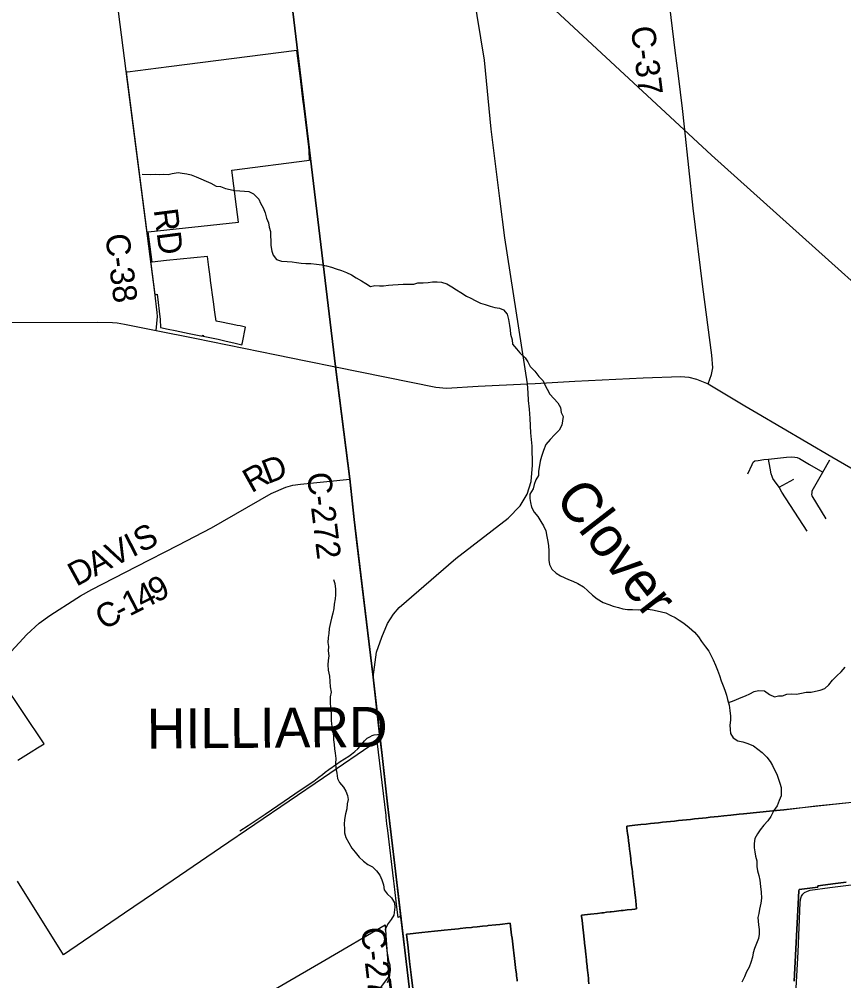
# Model space of a CAD drawing. Extents: x 114604 to 551442, y 316898 to 567001.
# Drawn here: x 149788 to 160095, y 405241 to 417252 of the extents above; entities that cross this region are included whole.
import ezdxf

# ---------------------------------------------------------------- set-up
doc = ezdxf.new("R2010")
doc.units = 0
for name, color, linetype in [('GE_P_Alignment_1000_Bearings', 7, 'Continuous'), ('GE_P_Alignment_100_Cardinal_Points', 7, 'Continuous'), ('GE_P_Alignment_100_Stations', 7, 'Continuous'), ('GE_P_Alignment_500_Bearings', 7, 'Continuous'), ('GE_P_Alignment_500_Distances', 7, 'Continuous'), ('PM_P_Cells', 7, 'Continuous'), ('PM_P_CL_Double_Solid', 7, 'Continuous'), ('PM_P_Stop_Line', 7, 'Continuous'), ('SH_Named_Boundary', 7, 'Continuous')]:
    doc.layers.add(name, color=color, linetype=linetype)

msp = doc.modelspace()

# ---------------------------------------------------------------- linework, layer by layer
at = {"layer": 'GE_P_Alignment_1000_Bearings'}
msp.add_lwpolyline([(147203, 425812), (147532, 425512), (151087, 422349), (154540, 419172), (158440, 415556), (161813, 412533), (168064, 407288)], dxfattribs=at)
at = {"layer": 'GE_P_Alignment_100_Cardinal_Points'}
msp.add_line((159289, 411408), (159471, 411506), dxfattribs=at)
for points in [[(158897, 411574), (158948, 411691), (158961, 411721), (158983, 411734), (159023, 411742), (159095, 411751), (159155, 411757), (159378, 411782), (159444, 411784), (159482, 411783), (159512, 411777), (159542, 411763), (159665, 411692), (159832, 411596)], [(159637, 410856), (159322, 411344), (159289, 411408), (159227, 411488), (159207, 411515), (159201, 411539), (159188, 411573), (159176, 411645), (159155, 411757)], [(159875, 411011), (159700, 411298), (159694, 411316), (159698, 411336), (159698, 411360), (159716, 411392), (159832, 411596), (159919, 411748)], [(152546, 407112), (152650, 407179), (152863, 407323), (153098, 407483), (153301, 407621), (153469, 407735), (153534, 407783), (153578, 407819), (153612, 407845), (153658, 407881), (153754, 407947), (153802, 407979), (153908, 408048), (153942, 408073), (153985, 408105), (154020, 408139), (154051, 408173), (154074, 408202), (154104, 408238), (154139, 408271), (154171, 408290), (154201, 408304), (154227, 408311), (154267, 408319), (154293, 408321)], [(159397, 402966), (159416, 403344), (159434, 403792), (159476, 404743), (159491, 405001), (159524, 405599), (159550, 406219), (159557, 406272), (159567, 406297), (159582, 406321), (159606, 406345), (159640, 406362), (159673, 406372), (159920, 406405), (160715, 406504), (161064, 406553), (161471, 406600)]]:
    msp.add_lwpolyline(points, dxfattribs=at)
at = {"layer": 'GE_P_Alignment_100_Stations'}
msp.add_lwpolyline([(151127, 416591), (151484, 413814), (151500, 413815), (151512, 413816), (151525, 413712), (151539, 413606), (151552, 413503), (151555, 413400), (151652, 413380), (151738, 413363), (151911, 413328), (152079, 413294), (152081, 413304), (152091, 413302), (152089, 413292), (152276, 413254), (152373, 413232), (152470, 413210), (152572, 413187), (152578, 413213), (152617, 413407), (152551, 413421), (152514, 413428), (152460, 413439), (152417, 413448), (152316, 413468), (152249, 413482), (152234, 413593), (152217, 413722), (152205, 413811), (152193, 413900), (152181, 413989), (152180, 414003), (152167, 414096), (152159, 414156), (152141, 414290), (151629, 414237), (151449, 414218), (151425, 414408), (151400, 414595), (152528, 414718), (152503, 414908), (152469, 415171), (152444, 415369), (153418, 415491), (153414, 415607), (153408, 415659), (153345, 416172), (153339, 416222), (153322, 416365), (153303, 416511), (153259, 416863), (151660, 416659), (151141, 416593)], close=True, dxfattribs=at)
for points in [[(149773, 407995), (149939, 408100), (150018, 408149), (150101, 408201), (149576, 408984)], [(154674, 405065), (154589, 405818), (154561, 406052), (154523, 406031), (154507, 406160), (154499, 406235), (154474, 406450), (154465, 406519), (154395, 407118), (154385, 407202), (154376, 407286), (154373, 407307), (154264, 408233), (153592, 407776), (152306, 406902), (151714, 406499), (151104, 406084), (150340, 405565), (149765, 406485)], [(160739, 407527), (159346, 407378), (159208, 407365), (158843, 407327), (158786, 407321), (158682, 407310), (158596, 407301), (158526, 407294), (158476, 407288), (158426, 407283), (158376, 407278), (158327, 407273), (158277, 407267), (158227, 407262), (158177, 407257), (158128, 407251), (158078, 407246), (158028, 407241), (157979, 407236), (157929, 407230), (157879, 407225), (157829, 407220), (157780, 407215), (157730, 407209), (157680, 407204), (157626, 407198), (157559, 407191), (157483, 407183), (157382, 407172), (157385, 407148), (157393, 407079), (157398, 407040), (157404, 406989), (157411, 406936), (157417, 406885), (157420, 406859), (157423, 406835), (157432, 406765), (157439, 406705), (157448, 406636), (157452, 406603), (157454, 406587), (157459, 406539), (157461, 406524), (157466, 406488), (157472, 406438), (157475, 406417), (157478, 406388), (157484, 406338), (157491, 406282), (157496, 406239), (157504, 406140), (157485, 406137), (157444, 406133), (157389, 406126), (157339, 406120), (157313, 406117), (157282, 406114), (157226, 406107), (157189, 406103), (157176, 406101), (157127, 406096), (157090, 406091), (157071, 406089), (157015, 406083), (156929, 406073), (156852, 406064), (156816, 406060), (156818, 406046), (156824, 405994), (156837, 405872), (156840, 405843), (156845, 405798), (156853, 405723), (156854, 405712), (156862, 405652), (156870, 405574), (156873, 405541), (156878, 405500), (156880, 405481), (156886, 405423), (156893, 405362), (156894, 405351), (156899, 405302), (156902, 405276), (156906, 405242), (156910, 405201)], [(156910, 405201), (156906, 405242), (156902, 405276), (156899, 405302), (156894, 405351), (156893, 405362), (156886, 405423), (156880, 405481), (156878, 405500), (156873, 405541), (156870, 405574), (156862, 405652), (156854, 405712), (156853, 405723), (156845, 405798), (156840, 405843), (156837, 405872), (156824, 405994), (156818, 406046), (156816, 406060), (156852, 406064), (156929, 406073), (157015, 406083), (157071, 406089), (157090, 406091), (157127, 406096), (157176, 406101), (157189, 406103), (157226, 406107), (157282, 406114), (157313, 406117), (157339, 406120), (157389, 406126), (157444, 406133), (157485, 406137), (157504, 406140), (157496, 406239), (157491, 406282), (157484, 406338), (157478, 406388), (157475, 406417), (157472, 406438), (157466, 406488), (157461, 406524), (157459, 406539), (157454, 406587), (157452, 406603), (157448, 406636), (157439, 406705), (157432, 406765), (157423, 406835), (157420, 406859), (157417, 406885), (157411, 406936), (157404, 406989), (157398, 407040), (157393, 407079), (157385, 407148), (157382, 407172), (157483, 407183), (157559, 407191), (157626, 407198), (157680, 407204), (157730, 407209), (157780, 407215), (157829, 407220), (157879, 407225), (157929, 407230), (157979, 407236), (158028, 407241), (158078, 407246), (158128, 407251), (158177, 407257), (158227, 407262), (158277, 407267), (158327, 407273), (158376, 407278), (158426, 407283), (158476, 407288), (158526, 407294), (158596, 407301), (158682, 407310), (158786, 407321), (158843, 407327), (159208, 407365), (159346, 407378), (159744, 407424), (160739, 407527)], [(159475, 405235), (159534, 406363), (159536, 406381), (159771, 406411), (159769, 406426), (159867, 406440), (159956, 406451), (160056, 406464), (160126, 406473)], [(160126, 406473), (160056, 406464), (159956, 406451), (159867, 406440), (159769, 406426), (159771, 406411), (159536, 406381), (159534, 406363), (159475, 405235)], [(151119, 404053), (153608, 405500), (154363, 405938), (154376, 405747), (154391, 405519), (154406, 405298), (154406, 405289), (154301, 405152)], [(156014, 405234), (156012, 405253), (156005, 405303), (156003, 405328), (155997, 405373), (155993, 405402), (155988, 405447), (155984, 405476), (155979, 405522), (155975, 405551), (155970, 405591), (155966, 405625), (155962, 405661), (155957, 405700), (155952, 405735), (155948, 405774), (155943, 405810), (155934, 405884), (155925, 405959), (155796, 405945), (155746, 405940), (155650, 405930), (155637, 405928), (155581, 405922), (155547, 405919), (155511, 405915), (155457, 405909), (155442, 405908), (155369, 405900), (155302, 405893), (155278, 405891), (155233, 405886), (155189, 405881), (155099, 405872), (155064, 405868), (154980, 405859), (154822, 405843), (154638, 405823), (154628, 405822), (154648, 405652), (154668, 405482), (154688, 405313), (154707, 405144)], [(154707, 405144), (154688, 405313), (154668, 405482), (154648, 405652), (154628, 405822), (154638, 405823), (154822, 405843), (154980, 405859), (155064, 405868), (155099, 405872), (155189, 405881), (155233, 405886), (155278, 405891), (155302, 405893), (155369, 405900), (155442, 405908), (155457, 405909), (155511, 405915), (155547, 405919), (155581, 405922), (155637, 405928), (155650, 405930), (155746, 405940), (155796, 405945), (155925, 405959), (155934, 405884), (155943, 405810), (155948, 405774), (155952, 405735), (155957, 405700), (155962, 405661), (155966, 405625), (155970, 405591), (155975, 405551), (155979, 405522), (155984, 405476), (155988, 405447), (155993, 405402), (155997, 405373), (156003, 405328), (156005, 405303), (156012, 405253), (156014, 405234)]]:
    msp.add_lwpolyline(points, dxfattribs=at)
at = {"layer": 'GE_P_Alignment_500_Bearings'}
for p, q in [((151482, 413838), (151126, 416605)), ((156141, 412699), (156238, 412704)), ((158398, 412697), (158858, 412425)), ((154212, 409032), (154010, 410717)), ((154678, 405038), (154560, 406037))]:
    msp.add_line(p, q, dxfattribs=at)
for points in [[(156141, 412699), (155858, 414520), (155797, 415014), (155689, 415878), (155605, 416740), (155468, 417584), (155400, 418105), (155368, 418372), (155368, 418377)], [(151126, 416605), (151031, 417347), (150967, 417870), (150956, 417939), (150949, 417965)], [(158077, 416139), (158027, 416545), (157989, 416861), (157920, 417410), (157910, 417494)], [(158398, 412697), (158442, 412813), (158458, 412898), (158445, 413056), (158334, 413911), (158214, 414894), (158105, 415909), (158077, 416139)], [(151501, 413366), (151516, 413537), (151514, 413587), (151482, 413838)], [(146171, 413762), (147883, 413563), (148391, 413514), (148808, 413476), (149273, 413462), (150762, 413470), (150955, 413465), (151014, 413458), (151106, 413444), (151501, 413366)], [(151501, 413366), (151983, 413267), (152596, 413143)], [(152596, 413143), (153006, 413059), (153370, 412985), (153741, 412910)], [(153741, 412910), (154994, 412656), (155129, 412644), (155523, 412670), (156141, 412699)], [(154010, 410717), (153976, 411002), (153921, 411507), (153741, 412910)], [(156238, 412704), (156735, 412730), (157588, 412772), (158058, 412790), (158160, 412781), (158256, 412756), (158398, 412697)], [(154212, 409032), (154255, 409346), (154320, 409535), (154390, 409703), (154466, 409821), (154537, 409903), (155246, 410515), (155899, 411019), (156051, 411173), (156137, 411321), (156186, 411479), (156205, 411683), (156199, 411918), (156182, 412086), (156176, 412264), (156165, 412381), (156154, 412488), (156148, 412585), (156141, 412699)], [(158858, 412425), (159010, 412335), (159944, 411785), (160420, 411511)], [(150555, 410048), (150697, 410130), (151256, 410417), (151774, 410682), (152192, 410899), (152939, 411329), (153119, 411407), (153210, 411431), (153306, 411445), (153921, 411507)], [(149458, 409139), (149485, 409158), (149557, 409218), (149640, 409305), (149882, 409568), (150039, 409709), (150172, 409802), (150509, 410022), (150555, 410048)], [(154560, 406037), (154484, 406679), (154393, 407448), (154324, 408053), (154293, 408321), (154212, 409032)]]:
    msp.add_lwpolyline(points, dxfattribs=at)
at = {"layer": 'GE_P_Alignment_500_Distances'}
for points in [[(149551, 424070), (152411, 424370), (152484, 423731), (152645, 422325), (152815, 420666), (152854, 420299), (153740, 412913), (153920, 411510), (153975, 411005), (154211, 409035), (154323, 408056), (154391, 407451), (154483, 406682), (155073, 401675)], [(155073, 401675), (154483, 406682), (154391, 407451), (154323, 408056), (154211, 409035), (153975, 411005), (153920, 411510), (153740, 412913), (152854, 420299)]]:
    msp.add_lwpolyline(points, dxfattribs=at)
at = {"layer": 'PM_P_Cells'}
for points in [[(151324, 415316), (151428, 415312), (151488, 415315), (151542, 415313), (151596, 415315), (151650, 415314), (151702, 415326), (151773, 415336), (151827, 415331), (151882, 415321), (151938, 415307), (152002, 415284), (152060, 415260), (152124, 415229), (152182, 415205), (152248, 415168), (152304, 415164), (152367, 415136), (152427, 415127), (152481, 415115), (152545, 415110), (152603, 415104), (152659, 415100), (152717, 415071), (152783, 415005), (152806, 414954), (152838, 414898), (152862, 414834), (152881, 414767), (152905, 414707), (152913, 414655), (152928, 414601), (152928, 414547), (152932, 414484), (152935, 414426), (152945, 414354), (152961, 414304), (153004, 414251), (153068, 414231), (153138, 414224), (153200, 414220), (153256, 414214), (153312, 414205), (153372, 414201), (153434, 414199), (153506, 414194), (153570, 414186), (153630, 414173), (153692, 414157), (153750, 414134), (153818, 414112), (153881, 414088), (153941, 414061), (154001, 414023), (154065, 413984), (154119, 413950), (154180, 413913), (154235, 413927), (154293, 413921), (154343, 413924), (154403, 413930), (154457, 413934), (154527, 413937), (154587, 413943), (154649, 413942), (154721, 413944), (154771, 413958), (154837, 413959), (154899, 413963), (154955, 413971), (155011, 413972), (155067, 413966), (155133, 413945), (155196, 413909), (155254, 413874), (155310, 413840), (155378, 413791), (155432, 413767), (155488, 413737), (155553, 413706), (155611, 413688), (155673, 413669), (155733, 413653), (155791, 413641), (155843, 413622), (155889, 413566), (155906, 413501), (155916, 413425), (155923, 413371), (155931, 413319), (155949, 413249), (155952, 413194), (156002, 413134), (156046, 413083), (156113, 413023), (156145, 412973), (156173, 412914), (156232, 412858), (156284, 412791), (156338, 412737), (156357, 412687)], [(156357, 412687), (156387, 412630), (156419, 412570), (156470, 412515), (156520, 412461), (156554, 412401), (156564, 412340), (156589, 412290), (156581, 412236), (156571, 412180), (156536, 412120), (156480, 412062), (156424, 412002), (156369, 411938), (156341, 411866), (156316, 411792), (156298, 411732), (156292, 411678), (156281, 411608), (156279, 411554), (156245, 411498), (156226, 411440), (156212, 411384), (156172, 411318), (156171, 411266), (156179, 411216), (156193, 411156), (156226, 411095), (156270, 411039), (156308, 410980), (156341, 410924), (156369, 410862), (156385, 410791), (156396, 410727), (156404, 410673), (156408, 410613), (156407, 410494), (156415, 410440), (156446, 410384), (156500, 410333), (156556, 410301), (156653, 410254), (156709, 410232), (156769, 410203), (156841, 410161), (156895, 410112), (156956, 410056), (157014, 410014), (157088, 409967), (157160, 409942), (157214, 409920), (157279, 409902), (157335, 409885), (157393, 409879), (157453, 409880), (157525, 409876), (157597, 409880), (157647, 409883), (157705, 409875), (157761, 409863), (157815, 409848), (157869, 409836), (157935, 409805), (157987, 409779), (158039, 409745), (158096, 409706), (158164, 409654), (158228, 409595), (158281, 409539), (158317, 409480), (158367, 409412), (158410, 409357), (158436, 409301), (158464, 409251), (158493, 409182), (158515, 409120), (158541, 409054), (158564, 408989), (158588, 408927), (158608, 408869), (158627, 408809), (158643, 408754), (158661, 408684), (158670, 408618), (158678, 408548), (158678, 408497), (158671, 408433), (158675, 408379), (158679, 408329), (158712, 408277), (158770, 408240), (158834, 408226), (158896, 408203), (158968, 408177), (159020, 408136), (159075, 408094), (159135, 408035), (159173, 407981), (159204, 407929), (159228, 407877), (159260, 407822)], [(153717, 410255), (153733, 410202), (153741, 410134), (153742, 410062), (153738, 410010), (153726, 409944), (153719, 409892), (153709, 409832), (153693, 409771), (153680, 409717), (153664, 409643), (153658, 409577), (153651, 409527), (153647, 409465), (153653, 409415), (153648, 409363), (153658, 409300), (153650, 409240), (153647, 409188), (153651, 409120), (153668, 409046), (153672, 408978), (153676, 408913), (153687, 408845), (153675, 408787), (153673, 408715), (153680, 408649), (153686, 408580), (153687, 408496), (153693, 408446), (153705, 408372), (153716, 408302), (153718, 408251), (153724, 408191), (153731, 408137), (153737, 408083), (153745, 408019), (153740, 407955), (153746, 407898), (153758, 407836), (153765, 407768), (153793, 407716), (153840, 407659), (153870, 407609), (153890, 407555), (153900, 407504), (153887, 407450), (153883, 407388), (153865, 407326), (153856, 407256), (153852, 407198), (153856, 407140), (153853, 407088), (153871, 407029), (153909, 406963), (153944, 406897), (153988, 406846), (154036, 406786), (154093, 406735), (154147, 406693), (154205, 406664), (154255, 406612), (154294, 406561), (154320, 406501), (154340, 406439), (154349, 406377), (154389, 406326), (154443, 406276), (154480, 406213), (154482, 406159), (154471, 406061), (154439, 406007), (154401, 405955), (154364, 405887), (154370, 405831), (154364, 405771), (154365, 405713), (154379, 405661), (154385, 405610), (154396, 405544), (154406, 405490), (154420, 405438), (154425, 405370), (154417, 405320), (154411, 405269), (154387, 405217)], [(158653, 408715), (158703, 408734), (158755, 408756), (158811, 408779), (158867, 408799), (158921, 408827), (158976, 408853), (159028, 408868), (159104, 408864), (159165, 408815), (159229, 408787), (159279, 408799), (159331, 408802), (159383, 408820), (159444, 408824), (159502, 408823), (159566, 408833), (159626, 408847), (159688, 408844), (159740, 408858), (159800, 408872), (159856, 408893), (159906, 408937), (159955, 408995), (160009, 409049), (160063, 409101), (160111, 409158)], [(159260, 407822), (159275, 407770), (159297, 407710), (159311, 407655), (159314, 407605), (159312, 407553), (159288, 407493), (159261, 407425), (159219, 407367), (159185, 407291), (159144, 407237), (159094, 407186), (159048, 407128), (159015, 407076), (158985, 407018), (158973, 406956), (158974, 406902), (158982, 406851), (158992, 406797), (159008, 406741), (159007, 406667), (159017, 406615), (159032, 406556), (159044, 406498), (159054, 406420), (159063, 406346), (159067, 406271), (159058, 406209), (159042, 406137), (159034, 406083), (159021, 406029), (159029, 405941), (159037, 405883), (159038, 405824), (159028, 405770), (159004, 405706), (158981, 405644), (158963, 405590), (158953, 405536), (158932, 405470), (158912, 405412), (158878, 405354), (158853, 405290), (158821, 405224)]]:
    msp.add_lwpolyline(points, dxfattribs=at)

# ---------------------------------------------------------------- texts
at = {"layer": 'PM_P_CL_Double_Solid'}
for s, rotation, p in [('C-37', 277.0473, (157432, 417151)), ('RD', 277.2937, (151469, 414871)), ('C-38', 277.2822, (150863, 414557)), ('D', 21.1717, (152896, 411444)), ('R', 29.1534, (152691, 411329)), ('C-272', 277.0234, (153383, 411577)), ('S', 27.0908, (151312, 410583)), ('I', 27.094, (151203, 410526)), ('V', 27.0952, (150968, 410406)), ('A', 27.197, (150733, 410286)), ('D', 28.6797, (150503, 410160)), ('4', 26.9945, (151332, 409873)), ('9', 26.9783, (151496, 409957)), ('1', 27.0818, (151167, 409789)), ('C', 28.3683, (150842, 409616)), ('-', 27.3035, (151058, 409733)), ('C-272', 276.7525, (154058, 405894))]:
    msp.add_text(s, height=300, rotation=rotation, dxfattribs=at).set_placement(p)
at = {"layer": 'PM_P_Stop_Line'}
msp.add_text('Clover', height=500, rotation=307.6809, dxfattribs=at).set_placement((156470, 411262))
at = {"layer": 'SH_Named_Boundary'}
msp.add_text('HILLIARD', height=500, rotation=0.4121, dxfattribs=at).set_placement((151385, 408141))

doc.saveas('drawing.dxf')
